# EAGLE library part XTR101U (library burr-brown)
4-20mA Current loop Transmitter
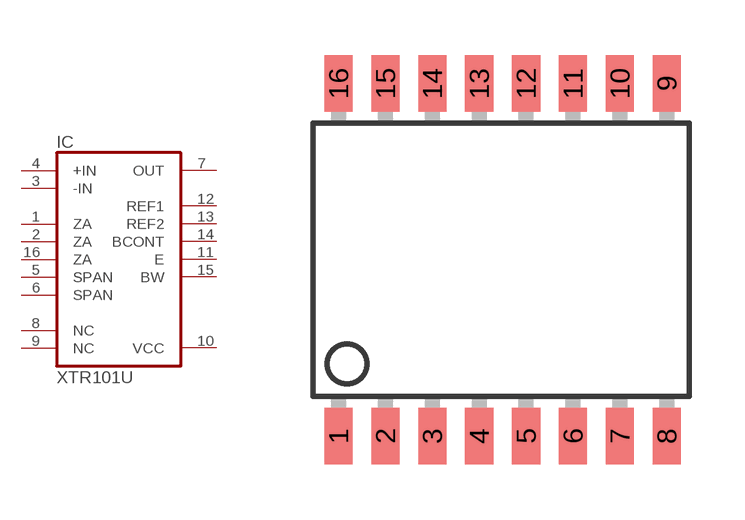
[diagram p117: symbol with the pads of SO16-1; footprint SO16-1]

Designator prefix IC

## XTR101U (MF: TEXAS INSTRUMENTS; MPN: XTR101AU; OC_FARNELL: 6543315; OC_NEWARK: 77C3626)  [SO16-1]
1  ZA  pas
2  ZA  pas
3  -IN  in
4  +IN  in
5  SPAN  pwr
6  SPAN  pwr
7  OUT  out
8  NC  nc
9  NC  nc
10  VCC  pwr
11  E  pas
12  REF1  out
13  REF2  out
14  BCONT  out
15  BW  pas
16  ZA  pwr

## Footprint SO16-1 (pad centres in mm)
Small Outline Package
smd 0.762 x 1.524: 1 -4.445,-4.775; 2 -3.175,-4.775; 3 -1.905,-4.775; 4 -0.635,-4.775; 5 0.635,-4.775; 6 1.905,-4.775; 7 3.175,-4.775; 8 4.445,-4.775; 9 4.445,4.775; 10 3.175,4.775; 11 1.905,4.775; 12 0.635,4.775; 13 -0.635,4.775; 14 -1.905,4.775; 15 -3.175,4.775; 16 -4.445,4.775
